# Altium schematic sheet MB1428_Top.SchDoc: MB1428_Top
size A4; Date: Not used; ApprovedBy: Not used; CheckedBy: Not used; Author: Not used; CompanyName: STMicroelectronics; DrawnBy: Not used; Engineer: Not used; Organization: Not used; Address1: Not used; Address2: Not used; Address3: Not used; Address4: Not used; DocumentNumber: Not used; Revision: Not used; SheetNumber: 2; SheetTotal: 12
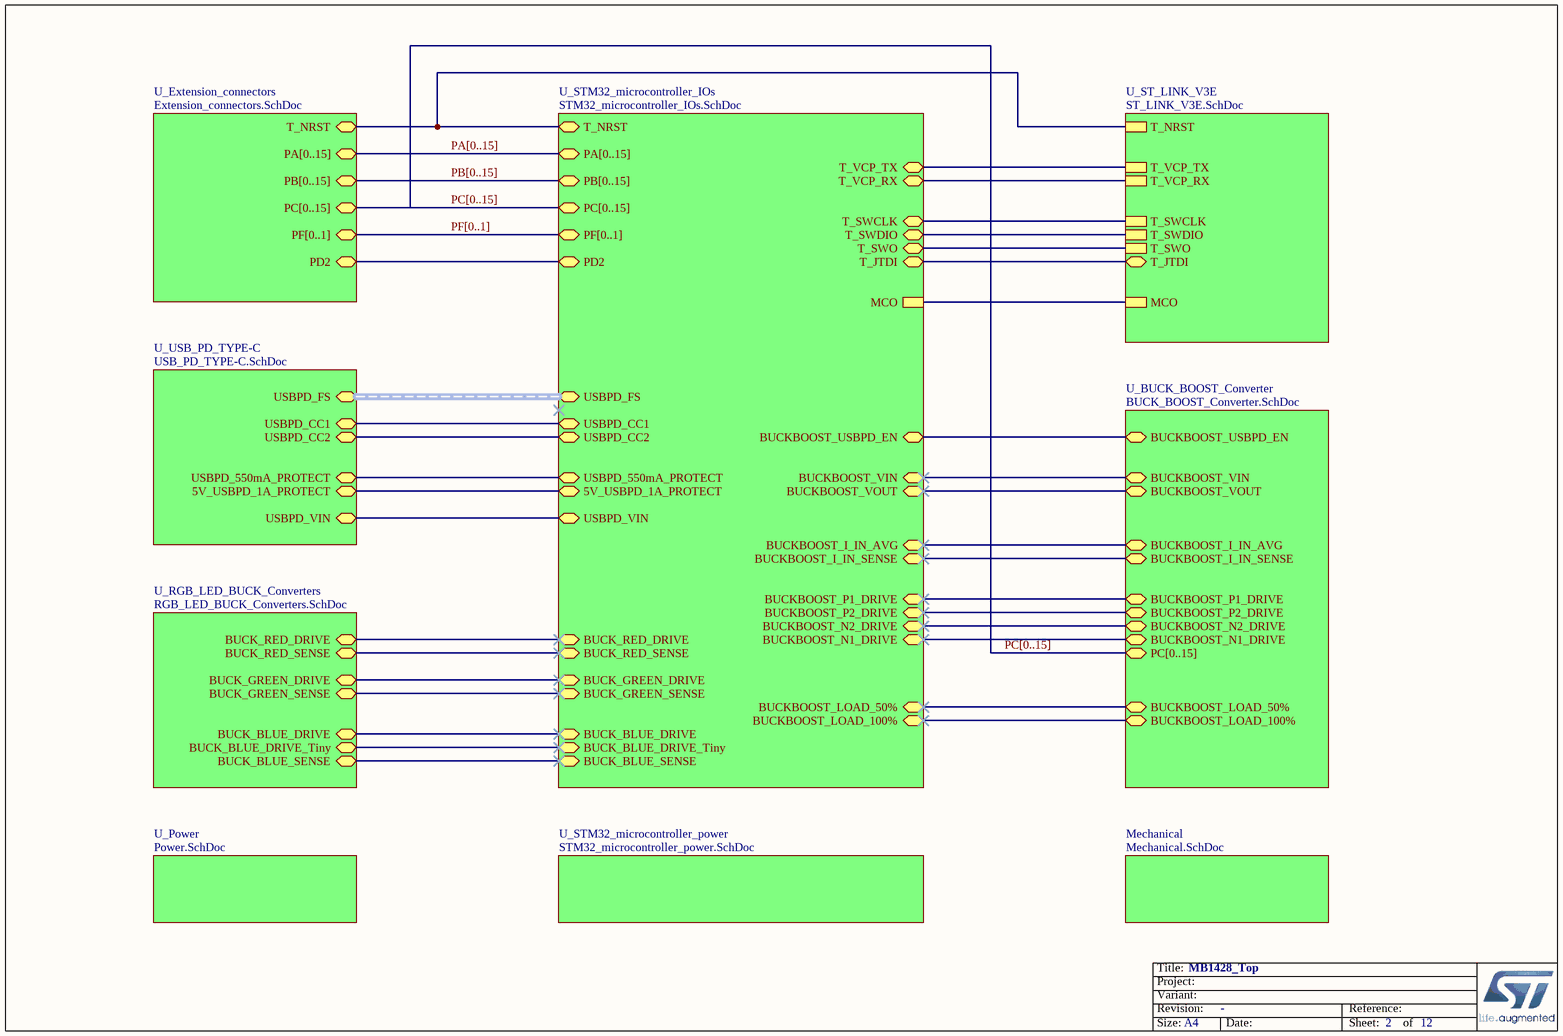
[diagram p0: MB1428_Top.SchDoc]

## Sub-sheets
Mechanical = Mechanical.SchDoc: no entries
U_BUCK_BOOST_Converter = BUCK_BOOST_Converter.SchDoc: PC[0..15] (bidir), BUCKBOOST_USBPD_EN, BUCKBOOST_VOUT, BUCKBOOST_VIN, BUCKBOOST_I_IN_SENSE, BUCKBOOST_I_IN_AVG, BUCKBOOST_P2_DRIVE, BUCKBOOST_P1_DRIVE, BUCKBOOST_N1_DRIVE, BUCKBOOST_N2_DRIVE, BUCKBOOST_LOAD_100%, BUCKBOOST_LOAD_50%
U_Extension_connectors = Extension_connectors.SchDoc: PA[0..15] (bidir), PB[0..15] (bidir), PC[0..15] (bidir), PF[0..1] (bidir), T_NRST, PD2
U_Power = Power.SchDoc: no entries
U_RGB_LED_BUCK_Converters = RGB_LED_BUCK_Converters.SchDoc: BUCK_GREEN_SENSE, BUCK_RED_DRIVE, BUCK_RED_SENSE, BUCK_GREEN_DRIVE, BUCK_BLUE_DRIVE, BUCK_BLUE_DRIVE_Tiny, BUCK_BLUE_SENSE
U_ST_LINK_V3E = ST_LINK_V3E.SchDoc: T_SWCLK, T_SWO, T_NRST, MCO, T_SWDIO, T_VCP_TX, T_VCP_RX, T_JTDI
U_STM32_microcontroller_IOs = STM32_microcontroller_IOs.SchDoc: PA[0..15] (bidir), PB[0..15] (bidir), PC[0..15] (bidir), PF[0..1] (bidir), MCO, PD2, T_NRST, T_VCP_TX, T_VCP_RX, T_SWCLK, T_SWO, T_SWDIO, T_JTDI, BUCKBOOST_USBPD_EN, BUCKBOOST_VIN, BUCKBOOST_VOUT, BUCKBOOST_I_IN_AVG, BUCKBOOST_I_IN_SENSE, BUCKBOOST_P2_DRIVE, BUCKBOOST_P1_DRIVE, BUCKBOOST_N1_DRIVE, BUCKBOOST_N2_DRIVE, BUCKBOOST_LOAD_100%, BUCKBOOST_LOAD_50%, USBPD_CC1, USBPD_CC2, 5V_USBPD_1A_PROTECT, USBPD_550mA_PROTECT, BUCK_GREEN_SENSE, BUCK_RED_DRIVE, BUCK_RED_SENSE, BUCK_GREEN_DRIVE, BUCK_BLUE_DRIVE, BUCK_BLUE_DRIVE_Tiny, BUCK_BLUE_SENSE, USBPD_FS (harness USBPDFS), USBPD_VIN
U_STM32_microcontroller_power = STM32_microcontroller_power.SchDoc: no entries
U_USB_PD_TYPE-C = USB_PD_TYPE-C.SchDoc: 5V_USBPD_1A_PROTECT, USBPD_CC1, USBPD_CC2, USBPD_550mA_PROTECT, USBPD_FS (harness USBPDFS), USBPD_VIN

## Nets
(unnamed): sheet U_Extension_connectors/T_NRST, sheet U_STM32_microcontroller_IOs/T_NRST, sheet U_ST_LINK_V3E/T_NRST
(unnamed): sheet U_Extension_connectors/PD2, sheet U_STM32_microcontroller_IOs/PD2  [a separate net that carries the same name]
(unnamed): sheet U_STM32_microcontroller_IOs/MCO, sheet U_ST_LINK_V3E/MCO  [a separate net that carries the same name]
(unnamed): sheet U_STM32_microcontroller_IOs/T_VCP_TX, sheet U_ST_LINK_V3E/T_VCP_TX  [a separate net that carries the same name]
(unnamed): sheet U_STM32_microcontroller_IOs/T_VCP_RX, sheet U_ST_LINK_V3E/T_VCP_RX  [a separate net that carries the same name]
(unnamed): sheet U_STM32_microcontroller_IOs/T_SWCLK, sheet U_ST_LINK_V3E/T_SWCLK  [a separate net that carries the same name]
(unnamed): sheet U_STM32_microcontroller_IOs/T_SWO, sheet U_ST_LINK_V3E/T_SWO  [a separate net that carries the same name]
(unnamed): sheet U_STM32_microcontroller_IOs/T_SWDIO, sheet U_ST_LINK_V3E/T_SWDIO  [a separate net that carries the same name]
(unnamed): sheet U_STM32_microcontroller_IOs/T_JTDI, sheet U_ST_LINK_V3E/T_JTDI  [a separate net that carries the same name]
(unnamed): sheet U_STM32_microcontroller_IOs/BUCKBOOST_USBPD_EN, sheet U_BUCK_BOOST_Converter/BUCKBOOST_USBPD_EN  [a separate net that carries the same name]
(unnamed): sheet U_STM32_microcontroller_IOs/BUCKBOOST_VIN, sheet U_BUCK_BOOST_Converter/BUCKBOOST_VIN  [a separate net that carries the same name]
(unnamed): sheet U_STM32_microcontroller_IOs/BUCKBOOST_VOUT, sheet U_BUCK_BOOST_Converter/BUCKBOOST_VOUT  [a separate net that carries the same name]
(unnamed): sheet U_STM32_microcontroller_IOs/BUCKBOOST_I_IN_AVG, sheet U_BUCK_BOOST_Converter/BUCKBOOST_I_IN_AVG  [a separate net that carries the same name]
(unnamed): sheet U_STM32_microcontroller_IOs/BUCKBOOST_I_IN_SENSE, sheet U_BUCK_BOOST_Converter/BUCKBOOST_I_IN_SENSE  [a separate net that carries the same name]
(unnamed): sheet U_STM32_microcontroller_IOs/BUCKBOOST_P2_DRIVE, sheet U_BUCK_BOOST_Converter/BUCKBOOST_P2_DRIVE  [a separate net that carries the same name]
(unnamed): sheet U_STM32_microcontroller_IOs/BUCKBOOST_P1_DRIVE, sheet U_BUCK_BOOST_Converter/BUCKBOOST_P1_DRIVE  [a separate net that carries the same name]
(unnamed): sheet U_STM32_microcontroller_IOs/BUCKBOOST_N1_DRIVE, sheet U_BUCK_BOOST_Converter/BUCKBOOST_N1_DRIVE  [a separate net that carries the same name]
(unnamed): sheet U_STM32_microcontroller_IOs/BUCKBOOST_N2_DRIVE, sheet U_BUCK_BOOST_Converter/BUCKBOOST_N2_DRIVE  [a separate net that carries the same name]
(unnamed): sheet U_STM32_microcontroller_IOs/BUCKBOOST_LOAD_100%, sheet U_BUCK_BOOST_Converter/BUCKBOOST_LOAD_100%  [a separate net that carries the same name]
(unnamed): sheet U_STM32_microcontroller_IOs/BUCKBOOST_LOAD_50%, sheet U_BUCK_BOOST_Converter/BUCKBOOST_LOAD_50%  [a separate net that carries the same name]
(unnamed): sheet U_STM32_microcontroller_IOs/USBPD_CC1, sheet U_USB_PD_TYPE-C/USBPD_CC1  [a separate net that carries the same name]
(unnamed): sheet U_STM32_microcontroller_IOs/USBPD_CC2, sheet U_USB_PD_TYPE-C/USBPD_CC2  [a separate net that carries the same name]
(unnamed): sheet U_STM32_microcontroller_IOs/5V_USBPD_1A_PROTECT, sheet U_USB_PD_TYPE-C/5V_USBPD_1A_PROTECT  [a separate net that carries the same name]
(unnamed): sheet U_STM32_microcontroller_IOs/USBPD_550mA_PROTECT, sheet U_USB_PD_TYPE-C/USBPD_550mA_PROTECT  [a separate net that carries the same name]
(unnamed): sheet U_STM32_microcontroller_IOs/BUCK_GREEN_SENSE, sheet U_RGB_LED_BUCK_Converters/BUCK_GREEN_SENSE  [a separate net that carries the same name]
(unnamed): sheet U_STM32_microcontroller_IOs/BUCK_RED_DRIVE, sheet U_RGB_LED_BUCK_Converters/BUCK_RED_DRIVE  [a separate net that carries the same name]
(unnamed): sheet U_STM32_microcontroller_IOs/BUCK_RED_SENSE, sheet U_RGB_LED_BUCK_Converters/BUCK_RED_SENSE  [a separate net that carries the same name]
(unnamed): sheet U_STM32_microcontroller_IOs/BUCK_GREEN_DRIVE, sheet U_RGB_LED_BUCK_Converters/BUCK_GREEN_DRIVE  [a separate net that carries the same name]
(unnamed): sheet U_STM32_microcontroller_IOs/BUCK_BLUE_DRIVE, sheet U_RGB_LED_BUCK_Converters/BUCK_BLUE_DRIVE  [a separate net that carries the same name]
(unnamed): sheet U_STM32_microcontroller_IOs/BUCK_BLUE_DRIVE_Tiny, sheet U_RGB_LED_BUCK_Converters/BUCK_BLUE_DRIVE_Tiny  [a separate net that carries the same name]
(unnamed): sheet U_STM32_microcontroller_IOs/BUCK_BLUE_SENSE, sheet U_RGB_LED_BUCK_Converters/BUCK_BLUE_SENSE  [a separate net that carries the same name]
(unnamed): sheet U_STM32_microcontroller_IOs/USBPD_VIN, sheet U_USB_PD_TYPE-C/USBPD_VIN  [a separate net that carries the same name]

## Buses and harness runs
bus PA[0..15] = sheet U_Extension_connectors/PA[0..15] = sheet U_STM32_microcontroller_IOs/PA[0..15]
bus PB[0..15] = sheet U_Extension_connectors/PB[0..15] = sheet U_STM32_microcontroller_IOs/PB[0..15]
bus PC[0..15] = sheet U_BUCK_BOOST_Converter/PC[0..15] = sheet U_Extension_connectors/PC[0..15] = sheet U_STM32_microcontroller_IOs/PC[0..15]
bus PF[0..1] = sheet U_Extension_connectors/PF[0..1] = sheet U_STM32_microcontroller_IOs/PF[0..1]
harness sheet U_STM32_microcontroller_IOs/USBPD_FS = sheet U_USB_PD_TYPE-C/USBPD_FS

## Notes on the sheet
- Cuttable part on PCB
